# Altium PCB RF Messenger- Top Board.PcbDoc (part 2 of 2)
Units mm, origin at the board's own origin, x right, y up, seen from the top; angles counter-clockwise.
Board outline 60 x 85 mm, 2 copper layers (Top Layer, Bottom Layer), stack 1.569 mm thick; 38 components, 18 nets, 106 pads, 20 vias.
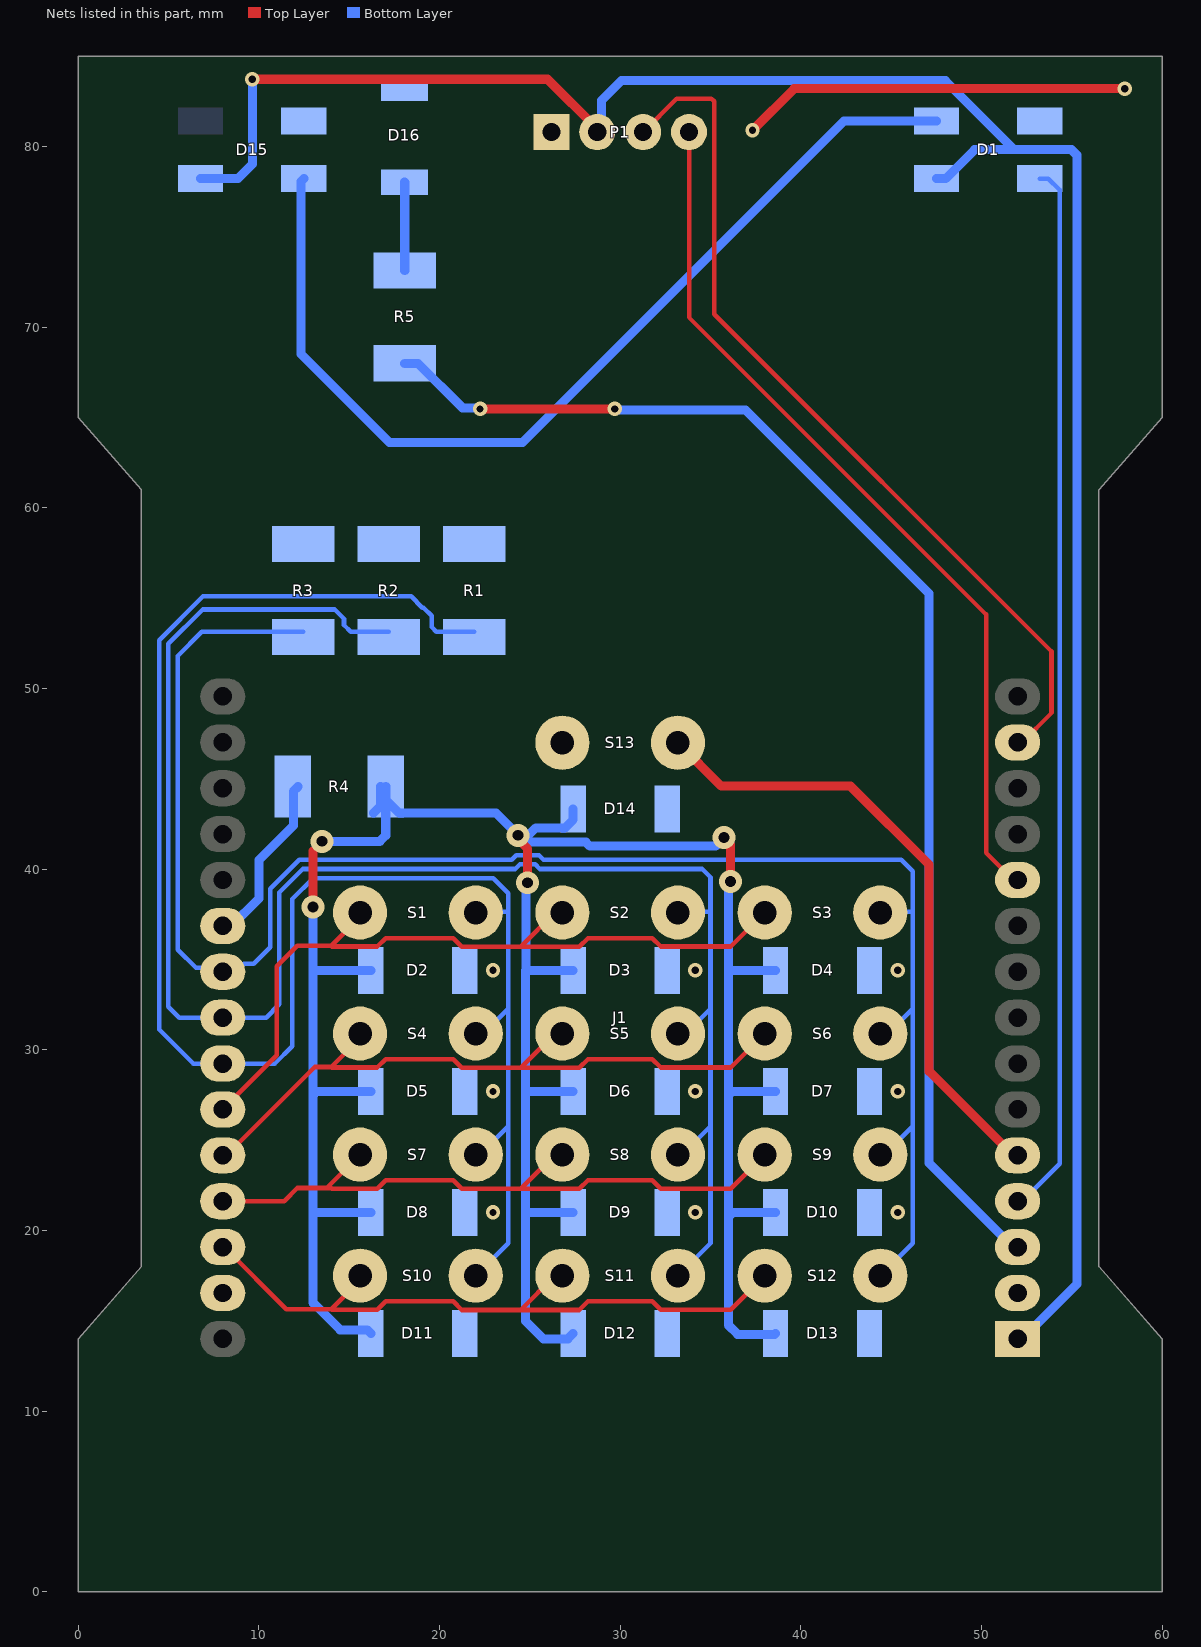
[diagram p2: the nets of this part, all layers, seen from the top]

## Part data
D1 D15: library part "1655 Neopixel", "Adafruit 1655 Neopixel 5.00mm L x 5.00mm W (footprint downloaded)"
D2 D3 D4 D5 D6 D7 D8 D9 D10 D11 D12 D13 D14 D16: "Generic LED"
J1: "15 Pin Connector"
P1: "Header, 4-Pin"
R1 R2 R3: library part "Resistor SMD 1206", "SMD Resistor 1206 (3216 Metric)"
R4 R5: library part Resistor, "Resistor"

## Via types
v1: diameter 0.8, hole 0.4, Top Layer to Bottom Layer, 14 vias
v2: diameter 1.27, hole 0.6, Top Layer to Bottom Layer, 6 vias

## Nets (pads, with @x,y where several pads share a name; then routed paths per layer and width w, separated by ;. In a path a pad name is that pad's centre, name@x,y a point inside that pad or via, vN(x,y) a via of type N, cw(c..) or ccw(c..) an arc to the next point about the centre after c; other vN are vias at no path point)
GND: D1.1 D2.2 D3.2 D4.2 D5.2 D6.2 D7.2 D8.2 D9.2 D10.2 D11.2 D12.2 D13.2 D14.2 D15.1 D16.2 J1.2 J1.29 P1.1 R1.2 R2.2 R3.2 S13.2 | length 21.6
  Top Layer w0.5: v1(37.325,80.9) 39.625,83.2 v1(57.925,83.2)
  other v1: 22.959,21 34.159,21 45.359,21 22.959,27.7 34.159,27.7 45.359,27.7 22.959,34.4 34.159,34.4 45.359,34.4
NetD1_2: D1.2 J1.4 | length 58.4
  Bottom Layer w0.25: J1.4@52,21.62 52.25,21.62 54.325,23.695 54.325,77.596 53.7,78.221 D1.2@53.228,78.221
NetD1_3: D1.3 D15.3 J1.1 P1.2 | length 130.6
  Top Layer w0.5: v1(9.637,83.725) 25.978,83.725 28.73,80.973 P1.2@28.73,80.8 ; J1.1@52,14 J1.1@52.25,14
  Bottom Layer w0.5: D15.3@6.772,78.221 8.834,78.221 9.637,79.024 v1(9.637,83.725) ; P1.2@28.73,80.8 28.968,81.038 28.968,82.55 30.068,83.65 47.998,83.65 51.823,79.825 ; D1.3@47.514,78.221 48.014,78.221 49.618,79.825 51.823,79.825 ; J1.1@52.25,14 55.275,17.025 55.275,79.532 54.982,79.825 51.823,79.825
NetD1_4: D1.4 D15.2 | length 54.4
  Bottom Layer w0.5: D15.2@12.486,78.221 12.325,78.06 12.325,68.525 17.225,63.625 24.6,63.625 42.396,81.421 D1.4@47.514,81.421
NetD2_1: D2.1 D3.1 D4.1 D5.1 D6.1 D7.1 D8.1 D9.1 D10.1 D11.1 D12.1 D13.1 D14.1 R4.2 | length 147
  Top Layer w0.5: v2(13,37.9) 13,41 ; v2(24.35,41.875) 24.35,41.65 24.874,41.126 v2(24.874,39.249) ; v2(35.75,41.75) 36.1,41.4 v2(36.1,39.325)
  Bottom Layer w0.5: v2(13,37.9) 13,34.5 ; v2(13.5,41.541) 16.691,41.541 17.024,41.874 R4.2@17.024,43.848 ; D11.1@16.2,14.3 16,14.5 14.5,14.5 13,16 13,21 ; D8.1@16.2,21 13,21 ; D5.1@16.2,27.7 13.2,27.7 13,27.5 ; D2.1@16.2,34.4 13.1,34.4 13,34.5 ; R4.2@16.339,43.098 16.724,43.483 R4.2@16.724,44.575 ; R4.2@17.024,44.575 R4.2@17.024,43.848 ; v2(24.874,39.249) 24.796,39.172 24.796,34.446 24.75,34.4 ; D12.1@27.4,14.3 27.1,14 25.75,14 24.75,15 24.75,21 ; D9.1@27.4,21 24.75,21 ; D6.1@27.4,27.7 24.8,27.7 24.75,27.75 ; D3.1@27.4,34.4 24.75,34.4 ; D14.1@27.4,43.338 27.4,42.738 26.95,42.287 25.339,42.287 v2@24.551,41.5 ; v2(35.75,41.75) 35.281,41.281 28.319,41.281 28.1,41.5 v2@24.551,41.5 ; v2(36.1,39.325) 35.996,39.221 35.996,34.5 ; D13.1@38.6,14.3 38.55,14.25 36.5,14.25 35.996,14.754 35.996,20.75 ; D10.1@38.6,21 36.246,21 35.996,20.75 ; D7.1@38.6,27.7 36.196,27.7 35.996,27.5 ; D4.1@38.6,34.4 36.096,34.4 35.996,34.5 ; 13,21 13,27.5 ; 13,27.5 13,34.5 ; R4.2@17.024,43.848 17.774,43.098 23.127,43.098 v2(24.35,41.875) 24.35,41.701 v2@24.551,41.5 ; 24.75,21 24.75,27.75 ; 24.75,27.75 24.75,34.4 ; 35.996,20.75 35.996,27.5 ; 35.996,27.5 35.996,34.5
NetD16_1: D16.1 R5.2 | length 4.9
  Bottom Layer w0.5: D16.1@18.05,78.025 18.075,78 R5.2@18.075,73.148
NetJ1_3: J1.3 R5.1 | length 72.7
  Top Layer w0.5: v1(22.247,65.475) v1(29.7,65.475)
  Bottom Layer w0.5: R5.1@18.075,68.002 18.802,68.002 21.271,65.532 22.19,65.532 v1(22.247,65.475) ; v1(29.7,65.475) 29.75,65.425 36.925,65.425 47.084,55.266 47.084,23.746 51.75,19.08 J1.3@52,19.08
NetJ1_5: J1.5 S13.1 | length 35
  Top Layer w0.5: S13.1@33.2,47 35.6,44.6 42.75,44.6 47.106,40.244 47.106,28.804 51.75,24.16 J1.5@52,24.16
NetJ1_11: J1.11 P1.4 | length 49.1
  Top Layer w0.25: P1.4@33.81,80.8 33.81,70.54 50.25,54.1 50.25,40.9 51.75,39.4 J1.11@52,39.4
NetJ1_14: J1.14 P1.3 | length 48.9
  Top Layer w0.25: P1.3@31.27,80.8 33.12,82.65 35.054,82.65 35.2,82.504 35.2,70.725 53.875,52.05 53.875,48.645 52.25,47.02 J1.14@52,47.02
NetJ1_21: J1.21 R4.1 | length 9.7
  Bottom Layer w0.5: J1.21@8,36.86 8.485,36.86 10,38.375 10,40.5 11.915,42.415 11.915,44.313 R4.1@12.177,44.575
NetJ1_22: J1.22 R3.1 S3.2 S6.2 S9.2 S12.2 | length 99
  Bottom Layer w0.254: R3.1@12.456,53.147 6.847,53.147 5.5,51.8 5.5,35.55 6.518,34.532 7.788,34.532 J1.22@8,34.32 8.722,34.32 9.16,34.758 9.708,34.758 10.631,35.681 10.631,38.919 12.237,40.525 23.994,40.525 24.242,40.773 25.505,40.773 25.753,40.525 45.55,40.525 46.2,39.875 46.2,37.65 ; S12.2@44.4,17.5 46.2,19.3 46.2,25.775 ; S3.2@44.45,37.65 46.2,37.65 ; S9.2@44.625,24.2 46.2,25.775 ; S6.2@44.825,30.9 46.2,32.275 ; 46.2,25.775 46.2,32.275 ; 46.2,32.275 46.2,37.65
NetJ1_23: J1.23 R2.1 S2.2 S5.2 S8.2 S11.2 | length 100.2
  Bottom Layer w0.254: R2.1@17.193,53.147 15.085,53.147 14.714,53.518 14.714,53.855 14.194,54.375 6.9,54.375 4.992,52.467 4.992,32.388 5.6,31.78 J1.23@8,31.78 10.4,31.78 11.139,32.519 11.139,38.709 12.438,40.008 24.195,40.008 24.453,40.265 25.294,40.265 25.552,40.008 34.554,40.008 35,39.562 35,37.65 ; S11.2@33.2,17.5 35,19.3 35,25.775 ; S2.2@33.25,37.65 35,37.65 ; S8.2@33.425,24.2 35,25.775 ; S5.2@33.625,30.9 35,32.275 ; 35,25.775 35,32.275 ; 35,32.275 35,37.65
NetJ1_24: J1.24 R1.1 S1.2 S4.2 S7.2 S10.2 | length 99.2
  Bottom Layer w0.254: R1.1@21.93,53.147 19.821,53.147 19.562,53.406 19.562,54.028 19.115,54.475 19.05,54.475 18.425,55.1 6.907,55.1 4.484,52.677 4.484,31.125 6.369,29.24 J1.24@8,29.24 10.89,29.24 11.85,30.2 11.85,38.35 13,39.5 22.975,39.5 23.8,38.675 23.8,37.65 ; S10.2@22,17.5 23.8,19.3 23.8,25.775 ; S7.2@22,24.2 22.225,24.2 23.8,25.775 ; S4.2@22,30.9 22.425,30.9 23.8,32.275 ; S1.2@22,37.6 22.05,37.65 23.8,37.65 ; 23.8,25.775 23.8,32.275 ; 23.8,32.275 23.8,37.65
NetJ1_25: J1.25 S1.1 S2.1 S3.1 | length 43.8
  Top Layer w0.254: J1.25@8,26.7 11,29.7 11,34.625 12.125,35.75 14,35.75 ; S1.1@15.6,37.6 15.6,37.35 14,35.75 ; S2.1@26.8,37.6 26.388,37.6 24.488,35.7 ; S3.1@38,37.6 36.119,35.719 32.245,35.719 31.783,36.181 28.217,36.181 27.736,35.7 24.488,35.7 ; 14,35.75 14.031,35.719 16.555,35.719 17.017,36.181 20.759,36.181 21.24,35.7 24.488,35.7
NetJ1_26: J1.26 S4.1 S5.1 S6.1 | length 39.3
  Top Layer w0.254: J1.26@7.99,23.941 13.099,29.05 14,29.05 ; S4.1@15.6,30.9 15.6,30.65 14,29.05 ; S5.1@26.8,30.9 26.388,30.9 24.488,29 ; S6.1@38,30.9 36.119,29.019 32.245,29.019 31.783,29.481 28.217,29.481 27.736,29 24.488,29 ; 14,29.05 14.031,29.019 16.555,29.019 17.017,29.481 20.759,29.481 21.24,29 24.488,29
NetJ1_27: J1.27 S7.1 S8.1 S9.1 | length 37.6
  Top Layer w0.254: J1.27@8,21.62 11.395,21.62 12.125,22.35 13.75,22.35 ; S7.1@15.6,24.2 13.75,22.35 ; S8.1@26.8,24.2 26.388,24.2 24.488,22.3 ; S9.1@38,24.2 36.119,22.319 32.245,22.319 31.783,22.781 28.217,22.781 27.736,22.3 24.488,22.3 ; 13.75,22.35 14,22.35 14.031,22.319 16.555,22.319 17.017,22.781 20.759,22.781 21.24,22.3 24.488,22.3
NetJ1_28: J1.28 S10.1 S11.1 S12.1 | length 38.6
  Top Layer w0.254: J1.28@8,19.08 8.095,19.08 11.525,15.65 14,15.65 ; S10.1@15.6,17.5 15.6,17.25 14,15.65 ; S11.1@26.8,17.5 26.388,17.5 24.488,15.6 ; S12.1@38,17.5 36.119,15.619 32.245,15.619 31.783,16.081 28.217,16.081 27.736,15.6 24.488,15.6 ; 14,15.65 14.031,15.619 16.555,15.619 17.017,16.081 20.759,16.081 21.24,15.6 24.488,15.6
pads on no net: D15.4 J1.6 J1.7 J1.8 J1.9 J1.10 J1.12 J1.13 J1.15 J1.16 J1.17 J1.18 J1.19 J1.20 J1.30

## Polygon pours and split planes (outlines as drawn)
GND on Bottom Layer "GND_L02_P002" (solid, pour order 2): 0,85 60,85 60,65 56.5,61 56.5,18 60,14 60,11.825 0,11.825 0,14 3.5,18 3.5,61 0,65
GND on Top Layer "GND_L01_P003" (solid, pour order 3): 3.5,52.425 56.5,52.425 56.5,18 60,14 60,11.825 0,11.825 0,14 3.5,18

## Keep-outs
Top Layer:
  rectangle: 38.3,33.5 44.1,35
  rectangle: 15.9,13.55 21.7,15.05
  rectangle: 15.9,33.5 21.7,35
  rectangle: 27.1,33.5 32.9,35
  rectangle: 38.3,26.8 44.1,28.3
  rectangle: 27.1,26.8 32.9,28.3
  rectangle: 15.9,26.8 21.7,28.3
  rectangle: 15.9,20.1 21.7,21.6
  rectangle: 27.1,20.1 32.9,21.6
  rectangle: 27.05,42.375 32.95,44.275
  rectangle: 38.3,13.55 44.1,15.05
  rectangle: 38.3,20.1 44.1,21.6
  rectangle: 27.1,13.55 32.9,15.05
Keep-Out Layer:
  lines w1.2: 0,0 60,0 60,14 56.5,18 56.5,61 60,65 60,85 0,85 0,65 3.5,61 3.5,18 0,14 0,0
  lines w2: 17.55,80.575 cw(c18.05,80.575) 18.05,81.075 ; 17.55,80.575 ccw(c18.05,80.575) 18.05,80.075 ; 17.55,80.575 17.55,80.575 ; 18.05,80.075 ccw(c18.05,80.575) 18.55,80.575 ; 18.05,80.075 18.05,80.075 ; 18.05,81.075 cw(c18.05,80.575) 18.55,80.575 ; 18.05,81.075 18.05,81.075 ; 18.55,80.575 18.55,80.575

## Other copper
Top Layer:

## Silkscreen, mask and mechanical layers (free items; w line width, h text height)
Top Overlay:
  lines w0.013: 0,0 0,3.48 ; 0,10.516 0,13.996 ; 60,0 60,3.48 ; 60,10.516 60,13.996
Bottom Overlay:
  text "RF Messenger- Top Board V2" at 56.971,6.098 h1.2
  text "Designed by: Angel Cruz" at 56.971,3.748 h1.2
Top Solder:
  lines w0.013: 0,3.48 0,10.516
  lines w2: 17.55,80.575 cw(c18.05,80.575) 18.05,81.075 ; 17.55,80.575 ccw(c18.05,80.575) 18.05,80.075 ; 17.55,80.575 17.55,80.575 ; 18.05,80.075 ccw(c18.05,80.575) 18.55,80.575 ; 18.05,80.075 18.05,80.075 ; 18.05,81.075 cw(c18.05,80.575) 18.55,80.575 ; 18.05,81.075 18.05,81.075 ; 18.55,80.575 18.55,80.575
  text "MAIN" at 27.115,42.45 h2.75
  text "1@#><" at 15.719,33.712 h2.2
  text "2ABC" at 27.436,33.5 h2.25
  text "3DEF" at 38.714,33.51 h2.25
  text "4GHI" at 16.552,26.8 h2.25
  text "5JKL" at 27.781,26.8 h2.25
  text "6MNO" at 38.373,26.8 h2.25
  text "7PQRS" at 15.71,20.18 h2.1
  text "8TUV" at 27.475,20.1 h2.25
  text "9WXYZ" at 38.1,20.098 h2.05
  text "0.?!,()-" at 27.105,13.8 h2.25
  text "SPACE" at 15.709,13.623 h2.1
  text "BCKSPC" at 38.072,13.619 h1.75
Mechanical 1:
  the board outline again, w0.1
